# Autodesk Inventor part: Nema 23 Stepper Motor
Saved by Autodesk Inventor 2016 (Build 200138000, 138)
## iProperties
Created: 2015-11
Part Number: Nema 23 Stepper Motor
Material: Generic
Document SubType Name: Modeling
Designer: John
Density: 1 g/cm^3
Appearance: Default
Author: John
Revision Number: ANY
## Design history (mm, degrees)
feature "Cut-Extrude7"
body "Solid1"
